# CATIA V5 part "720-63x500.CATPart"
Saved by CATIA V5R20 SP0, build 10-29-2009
Part number: 720-63x500
Definition: NONE
Nomenclature: 720-63x500
Source: Unknown
Description: 720-63x500
Bounding box of the stored display mesh (mm): x 0 to 500, y -31.5 to 31.5, z -31.5 to 31.5
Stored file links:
  C:\Users\Utente\Desktop\IO LAVORO\3D X SITO CF\X SITO\720\720-63x500.CATPart

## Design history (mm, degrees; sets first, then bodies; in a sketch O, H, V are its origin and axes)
Body1 "720-63x500" (main body)
  Solid1: solid without history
